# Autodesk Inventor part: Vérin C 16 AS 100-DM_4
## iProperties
Shininess: 20.0
Angle Display Precision: 2
Document Length Units: 11269
Document Angle Units: 11279
Document Time Units: 11290
Document Mass Units: 11283
Document Length Units Precision: 3
Document Angle Units Precision: 2
Created: 2002-02
Part Number: Vérin C 16 AS 100-DM_4
Material: Par défaut
Document SubType Name: Modélisation
Designer: Administrateur
Density: 0.0
Volumn: 0.0
Area: 0.0
PropertySet Name: Model Information
Control State: 0
Master: False
Checked Out: False
Author: Administrateur
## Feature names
1. Base1
